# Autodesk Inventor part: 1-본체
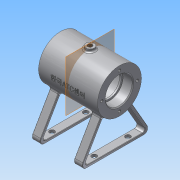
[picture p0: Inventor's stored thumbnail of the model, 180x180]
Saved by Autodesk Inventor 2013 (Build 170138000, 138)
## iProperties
Created: 2016-03
Part Number: 1-본체
Material: 알루미늄 6061
Document SubType Name: Modeling
Designer: Administrator
Density: 2.71 g/cm^3
Mass: 213.519 g
Surface Area: 333.696 cm^2
Volume: 78.7893 cm^3
Author: Administrator
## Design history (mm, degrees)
sketch "스케치1"
  geometry: C1 r 26 at (0, 0); 1 further point
  constraints: 1 centre point, 1 coincident
  dimensions: "d0" = 52 diameter of C1
extrude "돌출1" new body sketch "스케치1" distance "d2" = 70; taper "d3" = 0 deg
sketch "스케치2"
  geometry: C1 r 26 at (0, 0) reference; C2 r 16 at (0, 0)
  constraints: 1 centre point, 1 coincident
  dimensions: "d4" = 32 diameter of C2
extrude "돌출2" cut sketch "스케치2" distance "d6" = 12; taper "d7" = 0 deg
sketch "스케치3"
  geometry: C1 r 26 at (0, 0) reference; C2 r 16 at (0, 0)
  constraints: 1 centre point, 1 coincident
  dimensions: "d8" = 32 diameter of C2
extrude "돌출3" cut sketch "스케치3" distance "d10" = 12; taper "d11" = 0 deg
sketch "스케치4"
  geometry: C1 r 16 at (0, 0) reference; C2 r 14 at (0, 0)
  constraints: 1 centre point, 1 coincident
  dimensions: "d12" = 28 diameter of C2
extrude "돌출4" cut sketch "스케치4" distance "d14" = 2; taper "d15" = 0 deg
sketch "스케치5"
  geometry: C1 r 16 at (0, 0) reference; C2 r 14 at (0, 0)
  constraints: 1 centre point, 1 coincident
  dimensions: "d16" = 28 diameter of C2
extrude "돌출5" cut sketch "스케치5" distance "d18" = 2; taper "d19" = 0 deg
sketch "스케치6"
  geometry: C1 r 14 at (0, 0) reference; C2 r 21 at (0, 0)
  constraints: 1 centre point, 1 coincident
  dimensions: "d20" = 42 diameter of C2
extrude "돌출6" cut sketch "스케치6" distance "d22" = 42; taper "d23" = 0 deg
sketch "스케치7" dims "d24" = 42
  geometry: C1 r 16 at (0, 0) reference; C2 r 26 at (0, 0) reference; 2 further points
  constraints: 2 vertical alignment, 1 coincident, 2 other
hole "구멍1" sketch "스케치7" at (0, 21) diameter "d26" = 3.242; stored, may be unused: countersink angle "d30" = 90 deg, drill point angle "d32" = 118 deg; dims "d27" = 8, "d28" = 4, "d29" = 2, "d31" = 10
node "작업 평면1"
node "작업 평면2"
sketch "스케치8"
  geometry: L1 (26, 70)-(-26, 70) reference; L2 (-26, 0)-(26, 0) reference; L3 (-26, 0)-(-26, 70) reference; C1 r 5 at (0, 35); 3 further points
  constraints: 2 midpoint, 1 centre point, 1 horizontal alignment, 1 vertical alignment
  dimensions: "d37" = 10 diameter of C1
extrude "돌출7" join sketch "스케치8" stored distance "d39" = 10; taper "d40" = 0 deg
sketch "스케치9"
  geometry: C1 r 5 at (0, 0) reference; 2 further points
  constraints: 1 coincident
hole "구멍2" sketch "스케치9" at (0, 0) diameter "d41" = 5.188; stored, may be unused: countersink angle "d45" = 90 deg, drill point angle "d47" = 118 deg; dims "d42" = 10, "d43" = 4, "d44" = 2, "d46" = 10
node "작업 평면4"
  node "작업 평면3"
sketch "스케치10"
  geometry: L1 (-14.183, -21.791)-(-37.398, -62); L2 (-37.398, -62)-(37.398, -62); L3 (37.398, -62)-(14.183, -21.791); L4 (0, 0)-(0, -62); L5 (-16.613, -20)-(-42.594, -65); L6 (-42.594, -65)-(42.594, -65); L7 (42.594, -65)-(16.613, -20); A1 r 26 centre (0, 0) between (-16.613, -20) and (-14.183, -21.791) reference; 1 further point
  constraints: 14 end point, 4 point on circle, 1 horizontal, 1 midpoint, 1 perpendicular, 1 vertical alignment
  dimensions: "d52" = 3 distance between parallel lines of L1 L5; "d55" = 3 distance between parallel lines of L6 L2; "d56" = 3 distance between parallel lines of L7 L3; "d96" = 30 deg angle of L5 L4; "d98" = 60 deg angle of L7 L5; "d114" = 65 distance from line of L6 point (0, 0); "d115" = 45 vertical distance of L5.end L5.start
extrude "돌출8" join sketch "스케치10" distance "d58" = 10; taper "d59" = 0 deg
fillet "모깎기1" dims "d60" = 5
chamfer "모따기1" distance "d61" = 1; stored, may be unused: second distance "d62" = 2, angle "d63" = 45 deg
fillet "모깎기2" dims "d64" = 0.3
fillet "모깎기3" dims "d65" = 3
fillet "모깎기4" dims "d66" = 0.5
fillet "모깎기5" dims "d67" = 0.5
sketch "스케치11"
  geometry: L1 (-6.232, 0.5)-(-1.732, 0.5) reference; C1 r 3 at (12.202, -4.5); C2 r 3 at (52.202, -4.5); 2 further points
  constraints: 2 centre point, 1 equal radius, 1 horizontal alignment
  dimensions: "d68" = 6 diameter of C1; "d70" = 20 horizontal distance of C1.centre point (32.202, 55.5); "d71" = 5 distance from line of L1 C1.centre; "d72" = 40 distance of C2.centre C1.centre
extrude "돌출9" cut sketch "스케치11" stored distance "d73" = 10; taper "d74" = 0 deg
sketch "스케치12"
  geometry: L1 (0, 0)-(0, -26); L2 (0, 0)-(7.506, -28.012); 1 further point
  constraints: 4 end point, 1 vertical, 1 vertical alignment, 1 other
  dimensions: "d75" = 15 deg angle of L2 L1; "d76" = 29 distance of L1.start L2.end
node "작업 평면5"
fillet "모깎기6" dims "d88" = 2
fillet "모깎기7" dims "d89" = 3
node "작업 평면6"
sketch "스케치15"
  geometry: L1 (-26, 0)-(26, 0) reference; L2 (26, 0)-(26, 70) reference; 4 further points
  constraints: 2 midpoint, 1 horizontal alignment, 1 vertical alignment, 1 other
feature "엠보싱1" sketch "스케치15" dims "d0" = 52, "d92" = 0.5, "d93" = 0
sketch "스케치16"
  geometry: L1 (0, 0)-(0, -26); L2 (0, 0)-(7.506, -28.012); 1 further point
  constraints: 4 end point, 1 vertical, 1 vertical alignment, 1 other
  dimensions: "d99" = 15 deg angle of L2 L1; "d100" = 29 distance of L1.start L2.end
node "작업 평면7"
sketch "스케치17"
  geometry: L1 (26, -35)-(26, 35) reference; C1 r 6 at (0, 0); 2 further points
  constraints: 1 centre point, 1 horizontal alignment, 1 midpoint, 1 vertical alignment
  dimensions: "d101" = 12 diameter of C1
extrude "돌출11" join sketch "스케치17" stored distance "d103" = 10; taper "d104" = 0 deg
sketch "스케치18"
  geometry: C1 r 6 at (0, 0) reference; 2 further points
  constraints: 1 coincident
hole "구멍4" sketch "스케치18" at (0, 0) diameter "d105" = 5.188; stored, may be unused: countersink angle "d109" = 90 deg, drill point angle "d111" = 118 deg; dims "d106" = 10, "d107" = 4, "d108" = 2, "d110" = 10
fillet "모깎기9" dims "d112" = 2
fillet "모깎기10" dims "d113" = 3
node "솔리드1"
pattern_circular "원형 패턴1" dims angle "d34" = 360 deg
mirror "대칭1"
mirror "대칭2"
mirror "대칭3"
node "투영된 루프1"
other parameters: "d36" = 29, "d91" = -26
